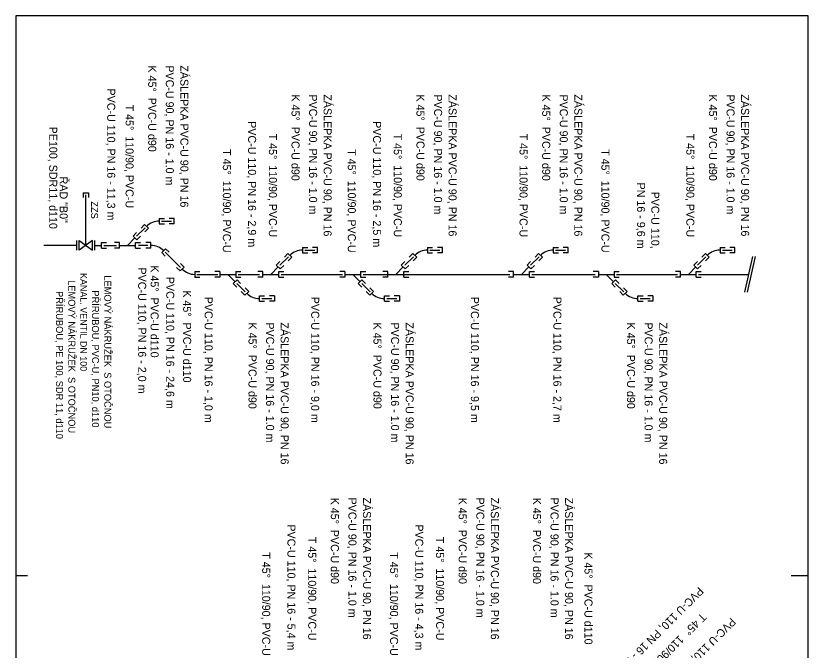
# Model space of a CAD drawing. Extents: x -549136 to -548786, y -1151900 to -1151213.
# Drawn here: x -549136 to -548987.5, y -1151683.1 to -1151564.2 of the extents above; entities that cross this region are included whole.
import ezdxf

# ---------------------------------------------------------------- set-up
doc = ezdxf.new("R2010")
doc.units = 0
doc.layers.add('Vrstva 2', color=7, linetype='Continuous')

msp = doc.modelspace()

# ---------------------------------------------------------------- linework, layer by layer
at = {"layer": 'Vrstva 2'}
for p, q in [((-548987.55, -1151564.17), (-549136.05, -1151564.17)), ((-549136.05, -1151564.17), (-549136.05, -1151669.17)), ((-548987.55, -1151669.17), (-548987.55, -1151564.17)), ((-549123.41, -1151597.39), (-549122.46, -1151597.39)), ((-549123.41, -1151597.39), (-549123.41, -1151598.26)), ((-549122.94, -1151607.21), (-549122.94, -1151597.74)), ((-549122.46, -1151597.39), (-549122.46, -1151598.26)), ((-549109.16, -1151602.16), (-549109.16, -1151603.17)), ((-549109.16, -1151602.16), (-549108.21, -1151602.16)), ((-549106.36, -1151602.16), (-549107.31, -1151602.16)), ((-549106.36, -1151603.17), (-549106.36, -1151602.16)), ((-549113.41, -1151605.51), (-549111.81, -1151603.92)), ((-549111.91, -1151603.3), (-549112.58, -1151603.97)), ((-549111.19, -1151604.01), (-549111.91, -1151603.3)), ((-549111.19, -1151604.01), (-549111.86, -1151604.69)), ((-549109.16, -1151603.17), (-549108.21, -1151603.17)), ((-549108.72, -1151602.67), (-549106.85, -1151602.67)), ((-549106.36, -1151603.17), (-549107.31, -1151603.17)), ((-549114.08, -1151605.47), (-549113.41, -1151604.8)), ((-549113.36, -1151606.19), (-549114.08, -1151605.47)), ((-549113.36, -1151606.19), (-549112.69, -1151605.52)), ((-549124.62, -1151608.11), (-549124.62, -1151606.31)), ((-549124.19, -1151608.11), (-549124.19, -1151606.31)), ((-549124.19, -1151606.31), (-549121.69, -1151608.11)), ((-549121.69, -1151606.31), (-549124.19, -1151608.11)), ((-549121.69, -1151608.11), (-549121.69, -1151606.31)), ((-549121.25, -1151608.11), (-549121.25, -1151606.31)), ((-549120.01, -1151606.7), (-549119.05, -1151606.7)), ((-549120.01, -1151607.72), (-549120.01, -1151606.7)), ((-549116.59, -1151606.7), (-549117.54, -1151606.7)), ((-549116.59, -1151607.72), (-549116.59, -1151606.7)), ((-549115.1, -1151607.21), (-549113.72, -1151605.83)), ((-549113.62, -1151607.72), (-549113.62, -1151606.7)), ((-549113.62, -1151606.7), (-549112.67, -1151606.7)), ((-549110.74, -1151606.7), (-549111.69, -1151606.7)), ((-549110.74, -1151607.72), (-549110.74, -1151606.7)), ((-549126.38, -1151607.21), (-549130.81, -1151607.21)), ((-549124.62, -1151607.21), (-549126.38, -1151607.21)), ((-549121.25, -1151607.21), (-549120.01, -1151607.21)), ((-549120.01, -1151607.72), (-549119.05, -1151607.72)), ((-549119.58, -1151607.21), (-549117.21, -1151607.21)), ((-549116.59, -1151607.72), (-549117.54, -1151607.72)), ((-549116.59, -1151607.21), (-549113.62, -1151607.21)), ((-549113.62, -1151607.72), (-549112.67, -1151607.72)), ((-549111.28, -1151607.21), (-549113.04, -1151607.21)), ((-549110.74, -1151607.72), (-549111.69, -1151607.72)), ((-549107.99, -1151607.84), (-549108.71, -1151608.56)), ((-549108.71, -1151608.56), (-549108.04, -1151609.23)), ((-549108.06, -1151608.49), (-549105.18, -1151611.37)), ((-549107.99, -1151607.84), (-549107.32, -1151608.51)), ((-549082.3, -1151607.6), (-549082.3, -1151608.61)), ((-549082.3, -1151607.6), (-549081.35, -1151607.6)), ((-549081.86, -1151608.11), (-549080, -1151608.11)), ((-549079.5, -1151607.6), (-549080.45, -1151607.6)), ((-549079.5, -1151608.61), (-549079.5, -1151607.6)), ((-549058.88, -1151607.6), (-549058.88, -1151608.61)), ((-549058.88, -1151607.6), (-549057.93, -1151607.6)), ((-549058.44, -1151608.11), (-549056.58, -1151608.11)), ((-549056.08, -1151607.6), (-549057.03, -1151607.6)), ((-549056.08, -1151608.61), (-549056.08, -1151607.6)), ((-549035.32, -1151607.6), (-549035.32, -1151608.61)), ((-549035.32, -1151607.6), (-549034.37, -1151607.6)), ((-549034.88, -1151608.11), (-549033.02, -1151608.11)), ((-549032.52, -1151607.6), (-549033.47, -1151607.6)), ((-549032.52, -1151608.61), (-549032.52, -1151607.6)), ((-549004.06, -1151607.6), (-549004.06, -1151608.61)), ((-549004.06, -1151607.6), (-549003.11, -1151607.6)), ((-549003.62, -1151608.11), (-549001.76, -1151608.11)), ((-549001.26, -1151607.6), (-549002.21, -1151607.6)), ((-549001.26, -1151608.61), (-549001.26, -1151607.6)), ((-549086.55, -1151610.95), (-549084.95, -1151609.36)), ((-549085.05, -1151608.74), (-549085.72, -1151609.41)), ((-549084.33, -1151609.45), (-549085.05, -1151608.74)), ((-549084.33, -1151609.45), (-549085, -1151610.13)), ((-549082.3, -1151608.61), (-549081.35, -1151608.61)), ((-549079.5, -1151608.61), (-549080.45, -1151608.61)), ((-549063.13, -1151610.95), (-549061.53, -1151609.36)), ((-549061.63, -1151608.74), (-549062.3, -1151609.41)), ((-549060.91, -1151609.45), (-549061.63, -1151608.74)), ((-549060.91, -1151609.45), (-549061.59, -1151610.13)), ((-549058.88, -1151608.61), (-549057.93, -1151608.61)), ((-549056.08, -1151608.61), (-549057.03, -1151608.61)), ((-549039.57, -1151610.95), (-549037.97, -1151609.36)), ((-549038.07, -1151608.74), (-549038.74, -1151609.41)), ((-549037.35, -1151609.45), (-549038.07, -1151608.74)), ((-549037.35, -1151609.45), (-549038.02, -1151610.13)), ((-549035.32, -1151608.61), (-549034.37, -1151608.61)), ((-549032.52, -1151608.61), (-549033.47, -1151608.61)), ((-549008.31, -1151610.95), (-549006.71, -1151609.36)), ((-549006.81, -1151608.74), (-549007.48, -1151609.41)), ((-549006.09, -1151609.45), (-549006.81, -1151608.74)), ((-549006.09, -1151609.45), (-549006.76, -1151610.13)), ((-549004.06, -1151608.61), (-549003.11, -1151608.61)), ((-549001.26, -1151608.61), (-549002.21, -1151608.61)), ((-548998, -1151609.32), (-548999.46, -1151615.98)), ((-548997.49, -1151609.32), (-548998.95, -1151615.98)), ((-549105.25, -1151612.02), (-549105.92, -1151611.35)), ((-549105.25, -1151612.02), (-549104.53, -1151611.3)), ((-549104.53, -1151611.3), (-549105.2, -1151610.63)), ((-549088.24, -1151612.65), (-549086.87, -1151611.27)), ((-549087.23, -1151610.91), (-549086.55, -1151610.24)), ((-549086.51, -1151611.63), (-549087.23, -1151610.91)), ((-549086.51, -1151611.63), (-549085.83, -1151610.96)), ((-549064.82, -1151612.65), (-549063.45, -1151611.27)), ((-549063.81, -1151610.91), (-549063.13, -1151610.24)), ((-549063.09, -1151611.63), (-549063.81, -1151610.91)), ((-549063.09, -1151611.63), (-549062.41, -1151610.96)), ((-549041.26, -1151612.65), (-549039.88, -1151611.27)), ((-549040.24, -1151610.91), (-549039.57, -1151610.24)), ((-549039.53, -1151611.63), (-549040.24, -1151610.91)), ((-549039.53, -1151611.63), (-549038.85, -1151610.96)), ((-549010, -1151612.65), (-549008.62, -1151611.27)), ((-549008.98, -1151610.91), (-549008.31, -1151610.24)), ((-549008.26, -1151611.63), (-549008.98, -1151610.91)), ((-549008.26, -1151611.63), (-549007.59, -1151610.96)), ((-549102.5, -1151612.14), (-549102.5, -1151613.16)), ((-549102.5, -1151612.14), (-549101.55, -1151612.14)), ((-549102.12, -1151612.65), (-549098.18, -1151612.65)), ((-549097.81, -1151612.14), (-549098.76, -1151612.14)), ((-549097.81, -1151612.14), (-549097.81, -1151613.16)), ((-549097.81, -1151612.65), (-549094.84, -1151612.65)), ((-549096.33, -1151612.65), (-549094.95, -1151614.03)), ((-549094.84, -1151612.14), (-549094.84, -1151613.16)), ((-549094.84, -1151612.14), (-549093.89, -1151612.14)), ((-549094.4, -1151612.65), (-549090.35, -1151612.65)), ((-549089.73, -1151612.14), (-549090.68, -1151612.14)), ((-549089.73, -1151613.16), (-549089.73, -1151612.14)), ((-549089.73, -1151612.65), (-549086.76, -1151612.65)), ((-549086.76, -1151613.16), (-549086.76, -1151612.14)), ((-549086.76, -1151612.14), (-549085.81, -1151612.14)), ((-549086.31, -1151612.65), (-549074.85, -1151612.65)), ((-549074.39, -1151612.14), (-549075.34, -1151612.14)), ((-549074.39, -1151612.14), (-549074.39, -1151613.16)), ((-549074.39, -1151612.65), (-549071.42, -1151612.65)), ((-549072.91, -1151612.65), (-549071.53, -1151614.03)), ((-549071.42, -1151612.14), (-549071.42, -1151613.16)), ((-549071.42, -1151612.14), (-549070.47, -1151612.14)), ((-549070.98, -1151612.65), (-549056.42, -1151612.65)), ((-549066.31, -1151612.14), (-549067.26, -1151612.14)), ((-549066.31, -1151613.16), (-549066.31, -1151612.14)), ((-549066.31, -1151612.65), (-549063.34, -1151612.65)), ((-549063.34, -1151613.16), (-549063.34, -1151612.14)), ((-549063.34, -1151612.14), (-549062.39, -1151612.14)), ((-549062.89, -1151612.65), (-549043.47, -1151612.65)), ((-549042.75, -1151612.14), (-549043.7, -1151612.14)), ((-549042.75, -1151613.16), (-549042.75, -1151612.14)), ((-549042.75, -1151612.65), (-549039.78, -1151612.65)), ((-549039.78, -1151613.16), (-549039.78, -1151612.14)), ((-549039.78, -1151612.14), (-549038.83, -1151612.14)), ((-549039.33, -1151612.65), (-549027.44, -1151612.65)), ((-549026.87, -1151612.14), (-549027.82, -1151612.14)), ((-549026.87, -1151612.14), (-549026.87, -1151613.16)), ((-549026.87, -1151612.65), (-549023.9, -1151612.65)), ((-549025.39, -1151612.65), (-549024.01, -1151614.03)), ((-549023.9, -1151612.14), (-549023.9, -1151613.16)), ((-549023.9, -1151612.14), (-549022.95, -1151612.14)), ((-549023.45, -1151612.65), (-549012.05, -1151612.65)), ((-549011.49, -1151612.14), (-549012.44, -1151612.14)), ((-549011.49, -1151613.16), (-549011.49, -1151612.14)), ((-549011.49, -1151612.65), (-549008.52, -1151612.65)), ((-549008.52, -1151613.16), (-549008.52, -1151612.14)), ((-549008.52, -1151612.14), (-549007.57, -1151612.14)), ((-549008.07, -1151612.65), (-548998.73, -1151612.65)), ((-549102.5, -1151613.16), (-549101.55, -1151613.16)), ((-549097.81, -1151613.16), (-549098.76, -1151613.16)), ((-549094.59, -1151613.67), (-549095.31, -1151614.39)), ((-549095.31, -1151614.39), (-549094.64, -1151615.06)), ((-549094.84, -1151613.16), (-549093.89, -1151613.16)), ((-549094.63, -1151614.34), (-549093.04, -1151615.94)), ((-549094.59, -1151613.67), (-549093.92, -1151614.34)), ((-549089.73, -1151613.16), (-549090.68, -1151613.16)), ((-549086.76, -1151613.16), (-549085.81, -1151613.16)), ((-549074.39, -1151613.16), (-549075.34, -1151613.16)), ((-549071.17, -1151613.67), (-549071.89, -1151614.39)), ((-549071.89, -1151614.39), (-549071.22, -1151615.06)), ((-549071.42, -1151613.16), (-549070.47, -1151613.16)), ((-549071.21, -1151614.34), (-549069.62, -1151615.94)), ((-549071.17, -1151613.67), (-549070.5, -1151614.34)), ((-549066.31, -1151613.16), (-549067.26, -1151613.16)), ((-549063.34, -1151613.16), (-549062.39, -1151613.16)), ((-549042.75, -1151613.16), (-549043.7, -1151613.16)), ((-549039.78, -1151613.16), (-549038.83, -1151613.16)), ((-549026.87, -1151613.16), (-549027.82, -1151613.16)), ((-549023.65, -1151613.67), (-549024.37, -1151614.39)), ((-549024.37, -1151614.39), (-549023.69, -1151615.06)), ((-549023.9, -1151613.16), (-549022.95, -1151613.16)), ((-549023.69, -1151614.34), (-549022.09, -1151615.94)), ((-549023.65, -1151613.67), (-549022.97, -1151614.34)), ((-549011.49, -1151613.16), (-549012.44, -1151613.16)), ((-549008.52, -1151613.16), (-549007.57, -1151613.16)), ((-549093.13, -1151616.56), (-549093.81, -1151615.89)), ((-549092.41, -1151615.84), (-549093.13, -1151616.56)), ((-549092.41, -1151615.84), (-549093.09, -1151615.17)), ((-549069.71, -1151616.56), (-549070.39, -1151615.89)), ((-549069, -1151615.84), (-549069.71, -1151616.56)), ((-549069, -1151615.84), (-549069.67, -1151615.17)), ((-549022.19, -1151616.56), (-549022.86, -1151615.89)), ((-549021.47, -1151615.84), (-549022.19, -1151616.56)), ((-549021.47, -1151615.84), (-549022.15, -1151615.17)), ((-549090.39, -1151617.7), (-549090.39, -1151616.68)), ((-549090.39, -1151616.68), (-549089.43, -1151616.68)), ((-549089.95, -1151617.19), (-549088.08, -1151617.19)), ((-549087.58, -1151616.68), (-549088.53, -1151616.68)), ((-549087.58, -1151616.68), (-549087.58, -1151617.7)), ((-549066.97, -1151617.7), (-549066.97, -1151616.68)), ((-549066.97, -1151616.68), (-549066.02, -1151616.68)), ((-549066.53, -1151617.19), (-549064.66, -1151617.19)), ((-549064.16, -1151616.68), (-549065.11, -1151616.68)), ((-549064.16, -1151616.68), (-549064.16, -1151617.7)), ((-549019.44, -1151617.7), (-549019.44, -1151616.68)), ((-549019.44, -1151616.68), (-549018.49, -1151616.68)), ((-549019.01, -1151617.19), (-549017.14, -1151617.19)), ((-549016.64, -1151616.68), (-549017.59, -1151616.68)), ((-549016.64, -1151616.68), (-549016.64, -1151617.7)), ((-549090.39, -1151617.7), (-549089.43, -1151617.7)), ((-549087.58, -1151617.7), (-549088.53, -1151617.7)), ((-549066.97, -1151617.7), (-549066.02, -1151617.7)), ((-549064.16, -1151617.7), (-549065.11, -1151617.7)), ((-549019.44, -1151617.7), (-549018.49, -1151617.7)), ((-549016.64, -1151617.7), (-549017.59, -1151617.7)), ((-549136.05, -1151669.17), (-549136.05, -1151774.17)), ((-549133.86, -1151669.17), (-549136.05, -1151669.17)), ((-548987.55, -1151669.17), (-548990.75, -1151669.17)), ((-548987.55, -1151774.17), (-548987.55, -1151669.17))]:
    msp.add_line(p, q, dxfattribs=at)
for centre, start, end in [((-549109.16, -1151606.04), 90, 135), ((-549110.74, -1151610.59), 45, 90), ((-549082.3, -1151611.48), 90, 135), ((-549058.88, -1151611.48), 90, 135), ((-549035.32, -1151611.48), 90, 135), ((-549004.06, -1151611.48), 90, 135), ((-549102.5, -1151609.27), 225, 270), ((-549090.39, -1151613.81), 225, 270), ((-549066.97, -1151613.81), 225, 270), ((-549019.44, -1151613.81), 225, 270)]:
    msp.add_arc(centre, 3.38, start, end, dxfattribs=at)

# ---------------------------------------------------------------- texts
for s, height, rotation, p in [('K 45°  PVC-U d90', 1.5, 270, (-549111.24, -1151573.48)), (' PVC-U 90, PN 16 - 1.0 m', 1.5, 270, (-549107.94, -1151572.9)), (' ZÁSLEPKA PVC-U 90, PN 16 ', 1.5, 270, (-549105.21, -1151572.89)), (' PVC-U 110, PN 16 - 11,3 m', 1.5, 270, (-549118.92, -1151577.24)), ('K 45°  PVC-U d90', 1.5, 270, (-549084.38, -1151578.92)), (' PVC-U 90, PN 16 - 1.0 m', 1.5, 270, (-549081.08, -1151578.34)), (' ZÁSLEPKA PVC-U 90, PN 16 ', 1.5, 270, (-549078.36, -1151578.33)), ('K 45°  PVC-U d90', 1.5, 270, (-549060.96, -1151578.92)), (' PVC-U 90, PN 16 - 1.0 m', 1.5, 270, (-549057.66, -1151578.34)), (' ZÁSLEPKA PVC-U 90, PN 16 ', 1.5, 270, (-549054.94, -1151578.33)), ('K 45°  PVC-U d90', 1.5, 270, (-549037.4, -1151578.92)), (' PVC-U 90, PN 16 - 1.0 m', 1.5, 270, (-549034.1, -1151578.34)), (' ZÁSLEPKA PVC-U 90, PN 16 ', 1.5, 270, (-549031.38, -1151578.33)), ('K 45°  PVC-U d90', 1.5, 270, (-549006.14, -1151578.92)), (' PVC-U 90, PN 16 - 1.0 m', 1.5, 270, (-549002.84, -1151578.34)), (' ZÁSLEPKA PVC-U 90, PN 16 ', 1.5, 270, (-549000.11, -1151578.33)), ('T 45°  110/90, PVC-U ', 1.5, 270, (-549115.48, -1151580.82)), (' PVC-U 110, PN 16 - 2,9 m', 1.5, 270, (-549092.52, -1151583.37)), (' PVC-U 110, PN 16 - 2,5 m', 1.5, 270, (-549069.1, -1151583.37)), ('PE100, SDR11, d110', 1.5, 270, (-549129.79, -1151584.95)), ('T 45°  110/90, PVC-U ', 1.5, 270, (-549088.62, -1151586.26)), ('T 45°  110/90, PVC-U ', 1.5, 270, (-549065.21, -1151586.26)), ('T 45°  110/90, PVC-U ', 1.5, 270, (-549041.64, -1151586.26)), ('T 45°  110/90, PVC-U ', 1.5, 270, (-549010.38, -1151586.26)), ('T 45°  110/90, PVC-U ', 1.5, 270, (-549097.25, -1151589.16)), ('T 45°  110/90, PVC-U ', 1.5, 270, (-549073.83, -1151589.16)), ('T 45°  110/90, PVC-U ', 1.5, 270, (-549026.3, -1151589.16)), ('ŘAD "B0"', 1.5, 270, (-549127.84, -1151594.32)), ('PN 16 - 9,6 m', 1.5, 270, (-549019.61, -1151595.44)), (' PVC-U 110, ', 1.5, 270, (-549016.95, -1151596.58)), ('ZZS', 1.3, 270, (-549121.94, -1151598.95)), (' PVC-U 110, PN 16 - 2,0 m', 1.5, 270, (-549113.12, -1151610.81)), ('K 45°  PVC-U d110', 1.5, 270, (-549110.79, -1151610.96)), ('KANAL. VENTIL DN 100', 1.25, 270, (-549123.97, -1151612.41)), ('LEMOVÝ NÁKRUŽEK  S OTOČNOU ', 1.3, 270, (-549119.47, -1151612.84)), ('LEMOVÝ NÁKRUŽEK  S OTOČNOU ', 1.3, 270, (-549126.21, -1151613.74)), (' PVC-U 110, PN 16 - 24,6 m', 1.5, 270, (-549107.86, -1151612.56)), ('PŘÍRUBOU, PE 100, SDR 11, d110', 1.3, 270, (-549128.51, -1151615.79)), ('PŘÍRUBOU, PVC-U, PN10, d110', 1.3, 270, (-549121.77, -1151615.66)), ('K 45°  PVC-U d110', 1.5, 270, (-549104.69, -1151615.64)), (' PVC-U 110, PN 16 - 1,0 m', 1.5, 270, (-549100.66, -1151616.29)), (' PVC-U 110, PN 16 - 9,0 m', 1.5, 270, (-549080.69, -1151616.29)), (' PVC-U 110, PN 16 - 9,5 m', 1.5, 270, (-549050.76, -1151616.29)), (' PVC-U 110, PN 16 - 2,7 m', 1.5, 270, (-549035.3, -1151616.29)), ('K 45°  PVC-U d90', 1.5, 270, (-549092.44, -1151621.68)), (' PVC-U 90, PN 16 - 1.0 m', 1.5, 270, (-549089.14, -1151621.1)), (' ZÁSLEPKA PVC-U 90, PN 16 ', 1.5, 270, (-549086.41, -1151621.1)), ('K 45°  PVC-U d90', 1.5, 270, (-549069.02, -1151621.68)), (' PVC-U 90, PN 16 - 1.0 m', 1.5, 270, (-549065.72, -1151621.1)), (' ZÁSLEPKA PVC-U 90, PN 16 ', 1.5, 270, (-549062.99, -1151621.1)), ('K 45°  PVC-U d90', 1.5, 270, (-549021.5, -1151621.68)), (' PVC-U 90, PN 16 - 1.0 m', 1.5, 270, (-549018.2, -1151621.1)), (' ZÁSLEPKA PVC-U 90, PN 16 ', 1.5, 270, (-549015.47, -1151621.1)), (' ZÁSLEPKA PVC-U 90, PN 16 ', 1.5, 270, (-549070.98, -1151653.94)), (' ZÁSLEPKA PVC-U 90, PN 16 ', 1.5, 270, (-549047.02, -1151653.94)), (' ZÁSLEPKA PVC-U 90, PN 16 ', 1.5, 270, (-549033.11, -1151653.94)), ('K 45°  PVC-U d90', 1.5, 270, (-549077.01, -1151654.52)), (' PVC-U 90, PN 16 - 1.0 m', 1.5, 270, (-549073.71, -1151653.95)), ('K 45°  PVC-U d90', 1.5, 270, (-549053.05, -1151654.52)), (' PVC-U 90, PN 16 - 1.0 m', 1.5, 270, (-549049.75, -1151653.95)), ('K 45°  PVC-U d90', 1.5, 270, (-549039.13, -1151654.52)), (' PVC-U 90, PN 16 - 1.0 m', 1.5, 270, (-549035.83, -1151653.95)), (' PVC-U 110, PN 16 - 5,4 m', 1.5, 270, (-549085.15, -1151658.98)), (' PVC-U 110, PN 16 - 4,3 m', 1.5, 270, (-549061.19, -1151658.98)), ('T 45°  110/90, PVC-U ', 1.5, 270, (-549081.25, -1151661.87)), ('T 45°  110/90, PVC-U ', 1.5, 270, (-549057.29, -1151661.87)), ('T 45°  110/90, PVC-U ', 1.5, 270, (-549089.87, -1151664.76)), ('T 45°  110/90, PVC-U ', 1.5, 270, (-549065.91, -1151664.76)), ('K 45°  PVC-U d110', 1.5, 270, (-549029.47, -1151664.77)), (' PVC-U 110, PN 16 - 1,3 m', 1.5, 225, (-549007.65, -1151670.79)), ('T 45°  110/90, PVC-U ', 1.5, 225, (-549007.53, -1151676.04)), (' PVC-U 110, PN 16 - 6,4 m', 1.5, 225, (-549001.6, -1151676.55))]:
    msp.add_text(s, height=height, rotation=rotation, dxfattribs=at).set_placement(p)

doc.saveas('drawing.dxf')
